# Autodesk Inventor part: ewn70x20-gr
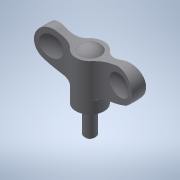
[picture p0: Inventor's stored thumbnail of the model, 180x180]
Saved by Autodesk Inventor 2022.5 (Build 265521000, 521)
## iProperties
Created: 2016-12
Part Number: ewn70x20-gr
Material: 一般
Document SubType Name: Modeling
Designer: imaocorp
Density: 1 g/cm^3
Appearance: 既定
Author: imaocorp
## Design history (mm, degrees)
node "ewn70x20-gr.x_t1"
node "ewn70x20-gr"
node "Base1"
